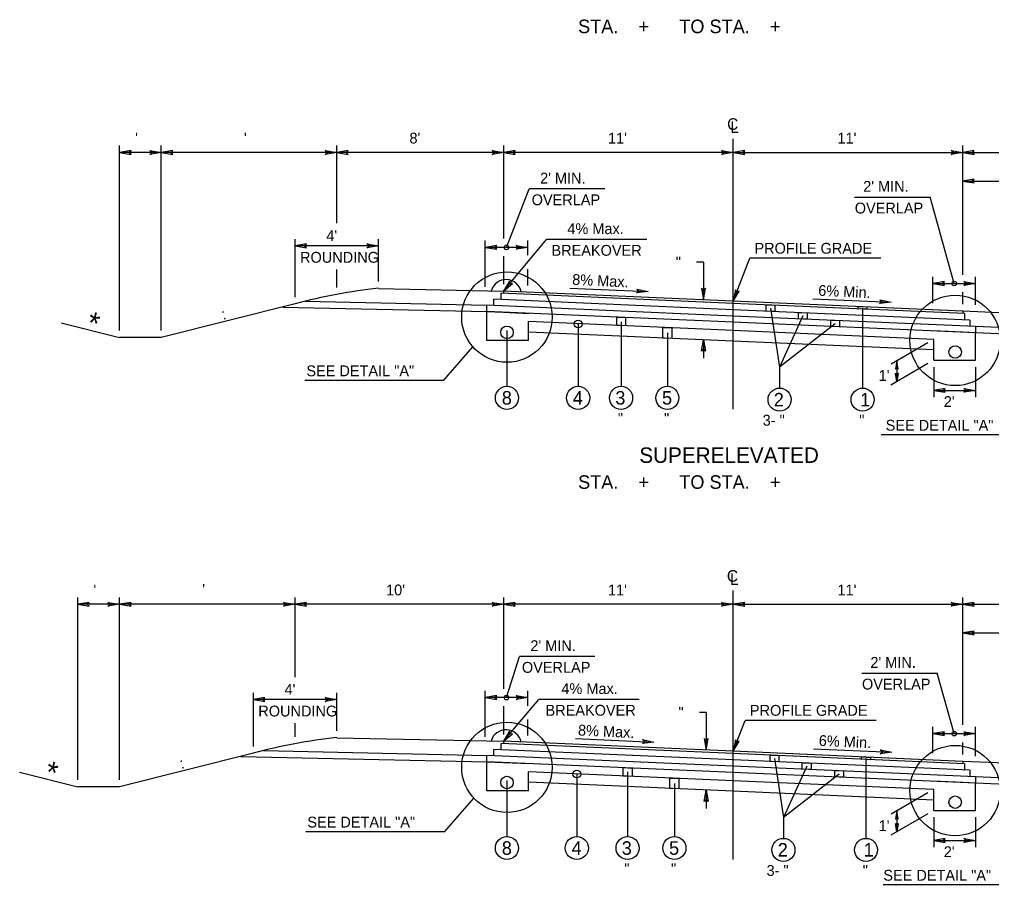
# Model space of a CAD drawing. Extents: x -540 to 1231, y -564 to 421.
# Drawn here: x 754.4 to 879.9, y 70.3 to 182.1 of the extents above; entities that cross this region are included whole.
import ezdxf

# ---------------------------------------------------------------- set-up
doc = ezdxf.new("R2010")
doc.units = 0
doc.layers.add('1', color=7, linetype='Continuous')
doc.layers.add('Des_ Drain_ Ftrs', color=7, linetype='Continuous')

msp = doc.modelspace()

# ---------------------------------------------------------------- linework, layer by layer
at = {"layer": '1'}
for p, q in [((767.3, 141.87), (767.3, 165.76)), ((772.69, 141.87), (772.69, 165.76)), ((795.35, 155.74), (795.35, 165.76)), ((816.91, 153.74), (816.91, 165.76)), ((846.54, 131.7), (846.54, 166.64)), ((876.18, 149.08), (876.18, 165.76)), ((772.69, 164.88), (767.3, 164.88)), ((795.35, 164.88), (772.69, 164.88)), ((816.91, 164.88), (795.35, 164.88)), ((846.54, 164.88), (816.91, 164.88)), ((846.54, 164.88), (876.18, 164.88)), ((876.18, 164.88), (897.73, 164.88)), ((876.17, 161.18), (903.92, 161.18)), ((817.27, 152.61), (820.18, 160.16)), ((829.95, 160.16), (820.18, 160.16)), ((862.21, 159.09), (871.97, 159.09)), ((875.08, 147.95), (871.97, 159.09)), ((789.97, 146.19), (789.97, 153.69)), ((800.74, 148.2), (800.74, 153.69)), ((814.53, 147.54), (814.53, 153.49)), ((816.9, 146.97), (822.44, 153.63)), ((820.02, 151.6), (820.02, 153.49)), ((835.41, 153.63), (822.44, 153.63)), ((800.74, 152.81), (789.97, 152.81)), ((820.02, 152.61), (814.53, 152.61)), ((816.91, 147.85), (816.91, 151.49)), ((842.7, 150.72), (841.82, 150.72)), ((842.7, 150.72), (842.7, 145.84)), ((846.54, 145.67), (848.68, 151.22)), ((865.6, 151.22), (848.68, 151.22)), ((795.35, 147.42), (795.35, 149.75)), ((820.02, 147.71), (820.02, 149.82)), ((872.33, 145.42), (872.33, 148.83)), ((877.82, 145.18), (877.82, 148.83)), ((800.74, 147.32), (816.9, 146.97)), ((846.54, 145.67), (816.9, 146.97)), ((816.9, 146.97), (816.9, 146.67)), ((825.44, 147.36), (835.56, 146.92)), ((872.33, 147.95), (877.82, 147.95)), ((791.26, 145.65), (814.67, 145.14)), ((846.54, 144.56), (815.64, 145.91)), ((815.64, 145.1), (815.64, 145.91)), ((846.54, 145.37), (816.56, 146.68)), ((816.56, 145.87), (816.56, 146.68)), ((876.18, 144.38), (846.54, 145.67)), ((856.83, 145.98), (866.95, 145.53)), ((876.18, 145.26), (876.18, 146.82)), ((789.97, 145.31), (772.69, 140.99)), ((788.37, 144.91), (814.72, 144.33)), ((846.54, 143.75), (814.72, 145.14)), ((814.72, 144.33), (814.72, 145.14)), ((876.42, 144.07), (846.54, 145.37)), ((877.12, 143.23), (846.54, 144.56)), ((851.36, 144.76), (852.53, 137.13)), ((863.25, 144.77), (863.25, 134.43)), ((892.34, 143.67), (876.18, 144.38)), ((876.18, 144.38), (876.18, 144.08)), ((814.72, 140.58), (814.72, 144.33)), ((846.54, 142.94), (814.72, 144.33)), ((814.72, 144.33), (816.9, 144.24)), ((816.9, 144.24), (820.2, 144.09)), ((877.82, 142.39), (846.54, 143.75)), ((855.54, 143.77), (852.53, 137.13)), ((876.42, 144.07), (876.42, 143.26)), ((877.12, 143.23), (877.12, 142.42)), ((759.76, 142.87), (767.3, 140.99)), ((817.33, 141.88), (817.33, 141.88)), ((817.33, 141.88), (817.33, 134.67)), ((846.54, 141.87), (820.1, 143.02)), ((820.1, 140.58), (820.1, 143.02)), ((826.52, 142.72), (826.52, 134.67)), ((832.07, 143.01), (832.07, 134.67)), ((877.82, 141.58), (846.54, 142.94)), ((872.44, 140.73), (846.54, 141.87)), ((859.71, 142.76), (852.53, 137.13)), ((877.82, 142.39), (877.82, 141.58)), ((904.95, 141.2), (877.82, 142.39)), ((772.69, 140.99), (767.3, 140.99)), ((846.54, 140.52), (820.1, 141.67)), ((838.04, 141.59), (838.04, 134.67)), ((842.7, 140.69), (842.7, 138.32)), ((876.18, 141.65), (872.34, 141.82)), ((872.44, 138.04), (872.44, 140.73)), ((872.44, 140.73), (872.44, 140.73)), ((877.82, 141.58), (876.18, 141.65)), ((877.82, 138.04), (877.82, 141.58)), ((908.87, 140.22), (877.82, 141.58)), ((809.17, 135.47), (812.91, 139.79)), ((820.1, 140.58), (814.72, 140.58)), ((872.44, 139.39), (846.54, 140.52)), ((871.67, 140.29), (866.92, 137.55)), ((852.53, 137.13), (852.53, 134.43)), ((871.67, 137.6), (866.9, 134.84)), ((867.68, 137.99), (867.66, 135.28)), ((872.44, 138.04), (877.82, 138.04)), ((872.44, 137.16), (872.44, 133.27)), ((877.82, 137.16), (877.82, 133.27)), ((791.24, 135.47), (809.17, 135.47)), ((872.44, 134.15), (877.82, 134.15)), ((865.65, 128.44), (884.43, 128.44)), ((846.54, 73.55), (846.54, 108.28)), ((761.91, 83.84), (761.91, 107.4)), ((767.3, 83.84), (767.3, 107.4)), ((789.97, 97.11), (789.97, 107.4)), ((816.91, 95.6), (816.91, 107.4)), ((876.18, 90.94), (876.18, 107.4)), ((767.3, 106.52), (761.91, 106.52)), ((789.97, 106.52), (767.3, 106.52)), ((816.91, 106.52), (789.97, 106.52)), ((846.54, 106.52), (816.91, 106.52)), ((846.54, 106.52), (876.18, 106.52)), ((876.18, 106.52), (903.12, 106.52)), ((876.18, 102.82), (909.55, 102.82)), ((817.27, 94.47), (818.93, 99.77)), ((828.69, 99.77), (818.93, 99.77)), ((863.14, 97.61), (872.9, 97.61)), ((875.08, 89.81), (872.9, 97.61)), ((784.58, 88.16), (784.58, 95.1)), ((795.35, 94.22), (784.58, 94.22)), ((795.35, 90.17), (795.35, 95.1)), ((814.53, 89.41), (814.53, 95.35)), ((820.02, 94.47), (814.53, 94.47)), ((816.9, 88.82), (821.46, 94.23)), ((820.02, 93.4), (820.02, 95.35)), ((834.39, 94.23), (821.46, 94.23)), ((816.91, 89.7), (816.91, 93.34)), ((843.06, 92.56), (842.18, 92.56)), ((843.06, 92.56), (843.06, 87.68)), ((789.97, 89.39), (789.97, 91.16)), ((820.02, 89.56), (820.02, 91.63)), ((846.54, 87.53), (848.09, 91.53)), ((865, 91.53), (848.09, 91.53)), ((872.33, 87.28), (872.33, 90.69)), ((877.82, 86.9), (877.82, 90.69)), ((795.35, 89.29), (816.9, 88.82)), ((826.2, 89.17), (836.31, 88.72)), ((872.33, 89.81), (877.82, 89.81)), ((846.54, 87.23), (816.56, 88.54)), ((816.56, 87.73), (816.56, 88.54)), ((846.54, 87.53), (816.9, 88.82)), ((816.9, 88.82), (816.9, 88.52)), ((876.18, 87.11), (876.18, 88.68)), ((784.58, 87.28), (767.3, 82.96)), ((782.98, 86.88), (814.72, 86.19)), ((785.9, 87.63), (814.72, 87)), ((846.54, 85.61), (814.72, 87)), ((814.72, 86.19), (814.72, 87)), ((846.54, 86.42), (815.64, 87.77)), ((815.64, 86.96), (815.64, 87.77)), ((876.18, 86.23), (846.54, 87.53)), ((876.42, 85.92), (846.54, 87.23)), ((856.9, 87.84), (867.02, 87.4)), ((863.69, 86.62), (863.69, 76.29)), ((814.72, 82.43), (814.72, 86.19)), ((846.54, 84.8), (814.72, 86.19)), ((814.72, 86.19), (816.9, 86.09)), ((816.9, 86.09), (820.2, 85.95)), ((877.12, 85.08), (846.54, 86.42)), ((877.82, 84.24), (846.54, 85.61)), ((851.87, 86.6), (853.03, 78.97)), ((856.04, 85.61), (853.03, 78.97)), ((897.73, 85.29), (876.18, 86.23)), ((876.18, 86.23), (876.18, 85.93)), ((876.42, 85.92), (876.42, 85.11)), ((754.38, 84.84), (761.91, 82.96)), ((846.54, 83.72), (820.1, 84.88)), ((820.1, 82.43), (820.1, 84.88)), ((826.35, 84.6), (826.35, 76.52)), ((832.91, 84.86), (832.91, 76.52)), ((877.82, 83.43), (846.54, 84.8)), ((860.22, 84.6), (853.03, 78.97)), ((877.12, 85.08), (877.12, 84.27)), ((877.82, 84.24), (877.82, 83.43)), ((910.34, 82.82), (877.82, 84.24)), ((767.3, 82.96), (761.91, 82.96)), ((817.33, 83.74), (817.33, 83.74)), ((817.33, 83.74), (817.33, 76.52)), ((846.54, 82.37), (820.1, 83.53)), ((838.95, 83.39), (838.95, 76.52)), ((872.44, 82.59), (846.54, 83.72)), ((876.18, 83.51), (872.34, 83.67)), ((877.82, 83.43), (876.18, 83.51)), ((877.82, 79.9), (877.82, 83.43)), ((914.26, 81.84), (877.82, 83.43)), ((820.1, 82.43), (814.72, 82.43)), ((843.06, 82.53), (843.06, 80.16)), ((872.44, 81.24), (846.54, 82.37)), ((871.67, 82.15), (866.92, 79.4)), ((872.44, 79.9), (872.44, 82.59)), ((872.44, 82.59), (872.44, 82.59)), ((809.3, 77.18), (813.04, 81.5)), ((871.67, 79.46), (866.9, 76.7)), ((867.68, 79.84), (867.66, 77.14)), ((872.44, 79.9), (877.82, 79.9)), ((853.03, 78.97), (853.03, 76.29)), ((872.44, 79.02), (872.44, 75.13)), ((877.82, 79.02), (877.82, 75.13)), ((791.37, 77.18), (809.3, 77.18)), ((872.44, 76.01), (877.82, 76.01)), ((865.92, 70.32), (884.71, 70.32))]:
    msp.add_line(p, q, dxfattribs=at)
for points in [[(850.79, 145.19), (851.94, 145.14), (851.94, 144.33), (850.79, 144.38)], [(862.68, 144.97), (863.82, 144.92), (863.82, 144.62), (862.68, 144.67)], [(831.5, 143.6), (832.64, 143.55), (832.64, 142.47), (831.5, 142.52)], [(854.97, 144.19), (856.11, 144.14), (856.11, 143.33), (854.97, 143.38)], [(859.14, 143.2), (860.29, 143.15), (860.29, 142.34), (859.14, 142.39)], [(837.47, 142.26), (838.61, 142.21), (838.61, 140.86), (837.47, 140.91)], [(851.3, 87.02), (852.44, 86.97), (852.44, 86.16), (851.3, 86.21)], [(863.12, 86.8), (864.27, 86.75), (864.27, 86.45), (863.12, 86.5)], [(832.34, 85.42), (833.48, 85.37), (833.48, 84.29), (832.34, 84.34)], [(855.47, 86.03), (856.62, 85.98), (856.62, 85.17), (855.47, 85.22)], [(860.79, 84.99), (860.79, 84.18), (859.65, 84.23), (859.65, 85.04)], [(838.37, 84.08), (839.52, 84.03), (839.52, 82.68), (838.37, 82.73)]]:
    msp.add_lwpolyline(points, close=True, dxfattribs=at)
for centre, radius in [((817.27, 152.61), 0.3), ((817.33, 143.61), 5.84), ((875.08, 147.95), 0.3), ((875.2, 140.6), 5.84), ((826.52, 142.72), 0.5), ((817.33, 141.65), 0.808), ((875.21, 139.11), 0.808), ((817.33, 133.18), 1.49), ((826.52, 133.18), 1.49), ((832.07, 133.18), 1.49), ((838.04, 133.18), 1.49), ((852.53, 132.95), 1.49), ((863.25, 132.95), 1.49), ((817.27, 94.47), 0.3), ((817.33, 85.46), 5.84), ((875.08, 89.81), 0.3), ((875.2, 82.45), 5.84), ((817.33, 83.5), 0.808), ((826.35, 84.6), 0.5), ((875.21, 80.97), 0.808), ((817.33, 75.04), 1.49), ((826.35, 75.04), 1.49), ((832.91, 75.04), 1.49), ((838.95, 75.04), 1.49), ((853.03, 74.8), 1.49), ((863.69, 74.8), 1.49)]:
    msp.add_circle(centre, radius, dxfattribs=at)
for centre, radius, start, end in [((817.22, 146.45), 2, 12.002, 163.9183), ((807.64, 80.49), 67.19, 95.8897, 105.2483), ((802.25, 22.46), 67.19, 95.8911, 105.2497), ((817.2, 88.31), 2, 12.0711, 163.96)]:
    msp.add_arc(centre, radius, start, end, dxfattribs=at)
at = {"layer": 'Des_ Drain_ Ftrs'}
for points in [[(767.3, 164.88), (768.79, 164.63), (768.49, 164.88), (768.79, 165.13)], [(772.69, 164.88), (771.2, 164.63), (771.49, 164.88), (771.2, 165.13)], [(772.69, 164.88), (774.18, 164.63), (773.88, 164.88), (774.18, 165.13)], [(795.35, 164.88), (793.87, 164.63), (794.16, 164.88), (793.87, 165.13)], [(795.35, 164.88), (796.84, 164.63), (796.55, 164.88), (796.84, 165.13)], [(816.91, 164.88), (815.42, 164.63), (815.71, 164.88), (815.42, 165.13)], [(816.91, 164.88), (818.4, 164.63), (818.1, 164.88), (818.4, 165.13)], [(846.54, 164.88), (845.05, 164.63), (845.35, 164.88), (845.05, 165.13)], [(846.54, 164.88), (848.03, 164.63), (847.74, 164.88), (848.03, 165.13)], [(876.18, 164.88), (874.69, 164.63), (874.98, 164.88), (874.69, 165.13)], [(876.18, 164.88), (877.67, 164.63), (877.37, 164.88), (877.67, 165.13)], [(876.17, 161.18), (877.66, 160.93), (877.37, 161.18), (877.66, 161.43)], [(789.97, 152.81), (791.45, 152.56), (791.16, 152.81), (791.45, 153.06)], [(800.74, 152.81), (799.25, 152.56), (799.55, 152.81), (799.25, 153.06)], [(814.53, 152.61), (816.02, 152.37), (815.73, 152.61), (816.02, 152.86)], [(820.02, 152.61), (818.53, 152.37), (818.82, 152.61), (818.53, 152.86)], [(816.9, 146.97), (818.04, 147.95), (817.66, 147.88), (817.66, 148.27)], [(872.33, 147.95), (873.82, 147.7), (873.53, 147.95), (873.82, 148.2)], [(877.82, 147.95), (876.33, 147.7), (876.63, 147.95), (876.33, 148.2)], [(835.56, 146.92), (834.06, 146.74), (834.36, 146.97), (834.08, 147.23)], [(842.7, 145.84), (842.95, 147.33), (842.7, 147.03), (842.45, 147.33)], [(846.54, 145.67), (847.31, 146.97), (846.97, 146.79), (846.84, 147.15)], [(866.95, 145.53), (865.45, 145.35), (865.75, 145.59), (865.47, 145.85)], [(842.7, 140.69), (842.95, 139.2), (842.7, 139.49), (842.45, 139.2)], [(867.68, 137.99), (867.49, 136.9), (867.67, 137.12), (867.85, 136.9)], [(867.66, 135.28), (867.49, 136.37), (867.66, 136.15), (867.85, 136.36)], [(872.44, 134.15), (873.92, 133.91), (873.63, 134.15), (873.92, 134.4)], [(877.82, 134.15), (876.34, 133.91), (876.63, 134.15), (876.34, 134.4)], [(761.91, 106.52), (763.4, 106.27), (763.11, 106.52), (763.4, 106.77)], [(767.3, 106.52), (765.81, 106.27), (766.11, 106.52), (765.81, 106.77)], [(767.3, 106.52), (768.79, 106.27), (768.49, 106.52), (768.79, 106.77)], [(789.97, 106.52), (788.48, 106.27), (788.77, 106.52), (788.48, 106.77)], [(789.97, 106.52), (791.45, 106.27), (791.16, 106.52), (791.45, 106.77)], [(816.91, 106.52), (815.42, 106.27), (815.71, 106.52), (815.42, 106.77)], [(816.91, 106.52), (818.4, 106.27), (818.1, 106.52), (818.4, 106.77)], [(846.54, 106.52), (845.05, 106.27), (845.35, 106.52), (845.05, 106.77)], [(846.54, 106.52), (848.03, 106.27), (847.74, 106.52), (848.03, 106.77)], [(876.18, 106.52), (874.69, 106.27), (874.98, 106.52), (874.69, 106.77)], [(876.18, 106.52), (877.67, 106.27), (877.37, 106.52), (877.67, 106.77)], [(876.18, 102.82), (877.67, 102.57), (877.37, 102.82), (877.67, 103.06)], [(784.58, 94.22), (786.07, 93.97), (785.77, 94.22), (786.07, 94.46)], [(795.35, 94.22), (793.87, 93.97), (794.16, 94.22), (793.87, 94.46)], [(814.53, 94.47), (816.02, 94.22), (815.73, 94.47), (816.02, 94.72)], [(820.02, 94.47), (818.53, 94.22), (818.82, 94.47), (818.53, 94.72)], [(816.9, 88.82), (818.05, 89.8), (817.67, 89.73), (817.67, 90.12)], [(843.06, 87.68), (843.3, 89.17), (843.06, 88.87), (842.81, 89.17)], [(872.33, 89.81), (873.82, 89.56), (873.53, 89.81), (873.82, 90.06)], [(877.82, 89.81), (876.33, 89.56), (876.63, 89.81), (876.33, 90.06)], [(836.31, 88.72), (834.81, 88.54), (835.12, 88.78), (834.83, 89.04)], [(846.54, 87.53), (847.31, 88.83), (846.97, 88.64), (846.84, 89.01)], [(867.02, 87.4), (865.52, 87.22), (865.82, 87.45), (865.54, 87.72)], [(843.06, 82.53), (843.3, 81.04), (843.06, 81.33), (842.81, 81.04)], [(867.68, 79.84), (867.49, 78.76), (867.67, 78.97), (867.85, 78.76)], [(867.66, 77.14), (867.49, 78.22), (867.66, 78.01), (867.85, 78.22)], [(872.44, 76.01), (873.92, 75.76), (873.63, 76.01), (873.92, 76.26)], [(877.82, 76.01), (876.34, 75.76), (876.63, 76.01), (876.34, 76.26)]]:
    msp.add_lwpolyline(points, close=True, dxfattribs=at)

# ---------------------------------------------------------------- texts
at = {"layer": '1'}
for s, height, p in [('STA.    +      TO STA.    +     ', 1.75, (826.51, 180.28)), (" '", 1.4, (768.8, 166.03)), ("  '", 1.4, (782.33, 166.03)), ("8'", 1.4, (804.74, 166.03)), ("11'", 1.4, (830.38, 166.03)), ("11'", 1.4, (860.01, 166.03)), ("2' MIN.", 1.4, (821.61, 160.86)), ("2' MIN.", 1.4, (863.33, 159.79)), ('OVERLAP', 1.4, (820.52, 158.06)), ('OVERLAP', 1.4, (862.24, 156.99)), ('4% Max.', 1.4, (825.13, 154.33)), ("4'", 1.4, (794, 153.43)), ('PROFILE GRADE', 1.4, (849.29, 151.8)), ('ROUNDING', 1.4, (790.61, 150.63)), ('BREAKOVER', 1.4, (823.08, 151.53)), ('SEE DETAIL "A"', 1.4, (791.43, 135.97)), ('8', 1.75, (816.66, 132.31)), ('4', 1.75, (825.84, 132.31)), ('3', 1.75, (831.32, 132.31)), ('5', 1.75, (837.35, 132.31)), ('2', 1.75, (851.78, 132.07)), ('1', 1.75, (862.95, 132.07)), ("2'", 1.4, (873.73, 132)), (' "', 1.4, (831.13, 129.82)), (' "', 1.4, (837.1, 129.82)), ('3- "', 1.4, (850.35, 129.59)), (' "', 1.4, (862.3, 129.59)), ('SEE DETAIL "A"', 1.4, (866.23, 128.94)), ('SUPERELEVATED', 2, (834.42, 124.78)), ('STA.    +      TO STA.    +     ', 1.75, (826.51, 121.43)), (" '", 1.4, (763.41, 107.67)), ("  '", 1.4, (776.94, 107.74)), ("10'", 1.4, (801.72, 107.67)), ("11'", 1.4, (830.38, 107.67)), ("11'", 1.4, (860.01, 107.67)), ("2' MIN.", 1.4, (820.35, 100.47)), ("2' MIN.", 1.4, (864.26, 98.31)), ('OVERLAP', 1.4, (819.26, 97.67)), ('OVERLAP', 1.4, (863.17, 95.51)), ("4'", 1.4, (788.61, 94.83)), ('4% Max.', 1.4, (824.36, 94.93)), ('ROUNDING', 1.4, (785.22, 92.03)), ('BREAKOVER', 1.4, (822.31, 92.13)), ('PROFILE GRADE', 1.4, (848.7, 92.12)), ('SEE DETAIL "A"', 1.4, (791.55, 77.69)), ('8', 1.75, (816.66, 74.16)), ('4', 1.75, (825.67, 74.16)), ('3', 1.75, (832.15, 74.16)), ('5', 1.75, (838.26, 74.16)), ('2', 1.75, (852.29, 73.93)), ('1', 1.75, (863.39, 73.93)), ("2'", 1.4, (873.73, 73.86)), (' "', 1.4, (831.97, 71.68)), (' "', 1.4, (838, 71.68)), ('3- "', 1.4, (850.85, 71.44)), (' "', 1.4, (862.75, 71.44)), ('SEE DETAIL "A"', 1.4, (865.93, 70.82))]:
    msp.add_text(s, height=height, dxfattribs=at).set_placement(p)
for s, height, rotation, p in [('  "', 1.4, 0.1438, (838.09, 150.01)), ('8% Max.', 1.4, 357.3763, (825.73, 147.78)), ('6% Min.', 1.4, 357.3732, (857.5, 146.37)), (' : ', 1.4, 14.2282, (780.15, 143.13)), ('*', 2.8, 347.1521, (762.93, 141.63)), ("1'", 1.4, 0.1438, (865.33, 135.37)), ('  "', 1.4, 0.1438, (838.44, 91.85)), ('8% Max.', 1.4, 357.3756, (826.48, 89.58)), ('6% Min.', 1.4, 357.3731, (857.57, 88.24)), ('*', 2.8, 347.1521, (757.54, 83.61)), (' : ', 1.4, 14.2282, (774.76, 85.11)), ("1'", 1.4, 0.1438, (865.33, 77.23))]:
    msp.add_text(s, height=height, rotation=rotation, dxfattribs=at).set_placement(p)
at = {"layer": 'Des_ Drain_ Ftrs'}
for s, p in [('C', (845.76, 167.79)), ('L', (846.16, 167.39)), ('C', (845.73, 109.43)), ('L', (846.12, 109.03))]:
    msp.add_text(s, height=1.5, dxfattribs=at).set_placement(p)

doc.saveas('drawing.dxf')
